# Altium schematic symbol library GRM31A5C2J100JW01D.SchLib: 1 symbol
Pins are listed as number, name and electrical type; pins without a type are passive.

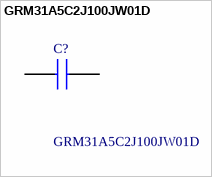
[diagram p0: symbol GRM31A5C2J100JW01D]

## GRM31A5C2J100JW01D
designator C?
Capacitor GRM31_0.20 L=3.2mm W=1.6mm T=1.0mm; Manufacturer_Name: Murata Electronics; Geometry.Height: 1mm
footprint CAPC3216X100N
pins: 1, 2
